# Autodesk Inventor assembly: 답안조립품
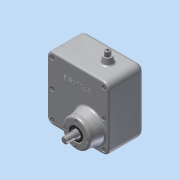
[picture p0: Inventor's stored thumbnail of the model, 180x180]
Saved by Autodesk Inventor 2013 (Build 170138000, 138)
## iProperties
Created: 2015-10
Part Number: 답안조립품
Document SubType Name: Assembly
Designer: Administrator
Author: Administrator
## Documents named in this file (15)
- C:\Users\Administrator\Desktop\351008V1009\답안조립품.iam
- C:\Users\Administrator\Desktop\351008V1009\본체.ipt
- C:\Users\Administrator\Desktop\351008V1009\M3 x 0.5.ipt
- C:\Users\Administrator\Desktop\351008V1009\M4 x 0.7.ipt
- C:\Users\Administrator\Desktop\351008V1009\가변 스프링.ipt
- C:\Users\Administrator\Desktop\351008V1009\로드 축.ipt
- C:\Users\Administrator\Desktop\351008V1009\로드.ipt
- C:\Users\Administrator\Desktop\351008V1009\베어링 6001.ipt
- C:\Users\Administrator\Desktop\351008V1009\베어링 6002.ipt
- C:\Users\Administrator\Desktop\351008V1009\슬라이드.ipt
- C:\Users\Administrator\Desktop\351008V1009\오일실 12 x 22.ipt
- C:\Users\Administrator\Desktop\351008V1009\오일실 15 x 25.ipt
- C:\Users\Administrator\Desktop\351008V1009\축 커버.ipt
- C:\Users\Administrator\Desktop\351008V1009\커버.ipt
- C:\Users\Administrator\Desktop\351008V1009\편심 축.ipt
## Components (11 placed, 3 different names)
1. M4 x 0.7:1
2. 가변 스프링:1
3. M4 x 0.7:2
4. M4 x 0.7:3
5. M4 x 0.7:4
6. M4 x 0.7:5
7. M4 x 0.7:6
8. M3 x 0.5:1
9. M3 x 0.5:2
10. M3 x 0.5:3
11. M3 x 0.5:4
